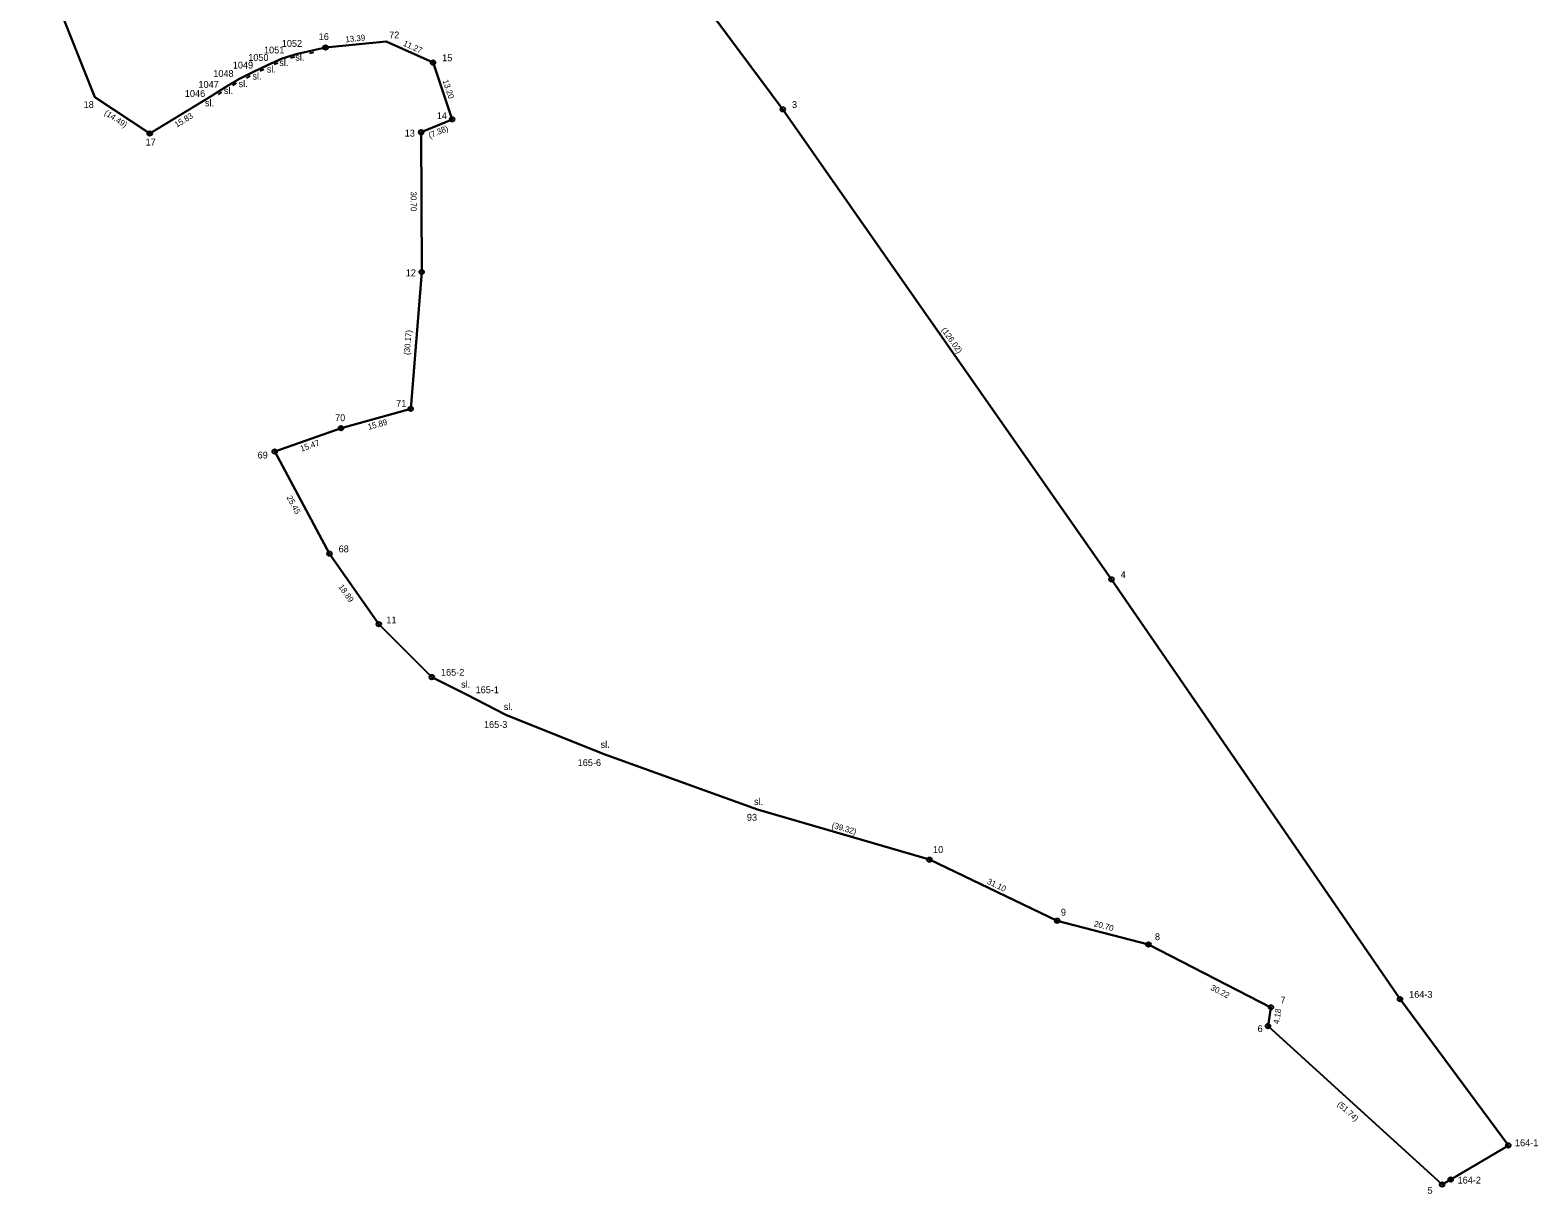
# Model space of a CAD drawing. Extents: x -555170 to -550532, y -1039598 to -1034701.
# Drawn here: x -553100.7 to -552769.4, y -1038100 to -1037844.3 of the extents above; entities that cross this region are included whole.
import ezdxf

# ---------------------------------------------------------------- set-up
doc = ezdxf.new("R2010")
doc.units = 0
for name, color, linetype in [('Vrstva 10', 7, 'Continuous'), ('Vrstva 40', 7, 'Continuous'), ('Vrstva 43', 7, 'Continuous'), ('Vrstva 48', 7, 'Continuous')]:
    doc.layers.add(name, color=color, linetype=linetype)

msp = doc.modelspace()

# ---------------------------------------------------------------- linework, layer by layer
at = {"layer": 'Vrstva 10'}
for p, q in [((-553047.12, -1037851.85), (-553046.31, -1037851.49)), ((-553043.44, -1037850.42), (-553042.58, -1037850.19)), ((-553039.23, -1037849.41), (-553038.37, -1037849.21)), ((-553053.18, -1037854.81), (-553052.39, -1037854.4)), ((-553050.14, -1037853.26), (-553049.34, -1037852.89)), ((-553059.34, -1037858.45), (-553058.58, -1037857.99)), ((-553056.15, -1037856.41), (-553055.39, -1037855.95))]:
    msp.add_line(p, q, dxfattribs=at)
at = {"layer": 'Vrstva 40'}
for p, q in [((-552935.31, -1037861.75), (-552967.96, -1037817.8)), ((-553100.71, -1037823.27), (-553086.52, -1037859.05)), ((-553041.94, -1037849.58), (-553035.79, -1037848.16)), ((-553035.79, -1037848.16), (-553022.47, -1037846.86)), ((-553022.47, -1037846.86), (-553012.18, -1037851.47)), ((-553051.75, -1037853.54), (-553048.52, -1037852.03)), ((-553048.52, -1037852.03), (-553045.34, -1037850.56)), ((-553045.34, -1037850.56), (-553041.94, -1037849.58)), ((-553012.18, -1037851.47), (-553007.97, -1037863.94)), ((-553057.92, -1037856.93), (-553054.87, -1037855.09)), ((-553054.87, -1037855.09), (-553051.75, -1037853.54)), ((-553060.93, -1037858.84), (-553057.92, -1037856.93)), ((-553086.52, -1037859.05), (-553074.43, -1037867.05)), ((-553074.43, -1037867.05), (-553060.93, -1037858.84)), ((-552863.09, -1037965.02), (-552935.31, -1037861.75)), ((-553007.97, -1037863.94), (-553014.78, -1037866.78)), ((-553014.78, -1037866.78), (-553014.68, -1037897.48)), ((-553014.68, -1037897.48), (-553017.09, -1037927.56)), ((-553017.09, -1037927.56), (-553032.4, -1037931.79)), ((-553032.4, -1037931.79), (-553046.98, -1037936.93)), ((-553046.98, -1037936.93), (-553034.93, -1037959.38)), ((-553034.93, -1037959.38), (-553024.08, -1037974.87)), ((-552799.7, -1038057.26), (-552863.09, -1037965.02)), ((-553024.08, -1037974.87), (-553012.44, -1037986.49)), ((-553012.44, -1037986.49), (-553004.83, -1037990.33)), ((-553004.83, -1037990.33), (-552996.15, -1037994.79)), ((-552996.15, -1037994.79), (-552974.77, -1038003.35)), ((-552974.77, -1038003.35), (-552940.85, -1038015.62)), ((-552940.85, -1038015.62), (-552903.1, -1038026.61)), ((-552903.1, -1038026.61), (-552875.05, -1038040.03)), ((-552875.05, -1038040.03), (-552854.97, -1038045.25)), ((-552854.97, -1038045.25), (-552828.06, -1038059.06)), ((-552775.89, -1038089.4), (-552799.7, -1038057.26)), ((-552828.06, -1038059.06), (-552828.71, -1038063.18)), ((-552828.71, -1038063.18), (-552790.43, -1038097.99)), ((-552788.56, -1038096.88), (-552775.89, -1038089.4)), ((-552790.43, -1038097.99), (-552788.56, -1038096.88))]:
    msp.add_line(p, q, dxfattribs=at)
at = {"layer": 'Vrstva 43'}
for p, q in [((-553035.79, -1037848.16), (-553035.79, -1037848.16)), ((-553022.47, -1037846.86), (-553022.47, -1037846.86)), ((-553048.52, -1037852.03), (-553048.52, -1037852.03)), ((-553045.34, -1037850.56), (-553045.34, -1037850.56)), ((-553041.94, -1037849.58), (-553041.94, -1037849.58)), ((-553012.18, -1037851.47), (-553012.18, -1037851.47)), ((-553054.87, -1037855.09), (-553054.87, -1037855.09)), ((-553051.75, -1037853.54), (-553051.75, -1037853.54)), ((-553057.92, -1037856.93), (-553057.92, -1037856.93)), ((-553086.52, -1037859.05), (-553086.52, -1037859.05)), ((-553060.93, -1037858.84), (-553060.93, -1037858.84)), ((-552935.31, -1037861.75), (-552935.31, -1037861.75)), ((-553007.97, -1037863.94), (-553007.97, -1037863.94)), ((-553074.43, -1037867.05), (-553074.43, -1037867.05)), ((-553014.78, -1037866.78), (-553014.78, -1037866.78)), ((-553014.68, -1037897.48), (-553014.68, -1037897.48)), ((-553017.09, -1037927.56), (-553017.09, -1037927.56)), ((-553032.4, -1037931.79), (-553032.4, -1037931.79)), ((-553046.98, -1037936.93), (-553046.98, -1037936.93)), ((-553034.93, -1037959.38), (-553034.93, -1037959.38)), ((-552863.09, -1037965.02), (-552863.09, -1037965.02)), ((-553024.08, -1037974.87), (-553024.08, -1037974.87)), ((-553012.44, -1037986.49), (-553012.44, -1037986.49)), ((-553004.83, -1037990.33), (-553004.83, -1037990.33)), ((-552996.15, -1037994.79), (-552996.15, -1037994.79)), ((-552974.77, -1038003.35), (-552974.77, -1038003.35)), ((-552940.85, -1038015.62), (-552940.85, -1038015.62)), ((-552903.1, -1038026.61), (-552903.1, -1038026.61)), ((-552875.05, -1038040.03), (-552875.05, -1038040.03)), ((-552854.97, -1038045.25), (-552854.97, -1038045.25)), ((-552799.7, -1038057.26), (-552799.7, -1038057.26)), ((-552828.06, -1038059.06), (-552828.06, -1038059.06)), ((-552828.71, -1038063.18), (-552828.71, -1038063.18)), ((-552775.89, -1038089.4), (-552775.89, -1038089.4)), ((-552788.56, -1038096.88), (-552788.56, -1038096.88)), ((-552790.43, -1038097.99), (-552790.43, -1038097.99))]:
    msp.add_line(p, q, dxfattribs=at)
for centre, radius in [((-553035.79, -1037848.16), 0.5), ((-553035.79, -1037848.16), 0.01), ((-553012.18, -1037851.47), 0.5), ((-553012.18, -1037851.47), 0.01), ((-552935.31, -1037861.75), 0.5), ((-552935.31, -1037861.75), 0.01), ((-553007.97, -1037863.94), 0.5), ((-553007.97, -1037863.94), 0.01), ((-553074.43, -1037867.05), 0.5), ((-553074.43, -1037867.05), 0.01), ((-553014.78, -1037866.78), 0.5), ((-553014.78, -1037866.78), 0.01), ((-553014.68, -1037897.48), 0.5), ((-553014.68, -1037897.48), 0.01), ((-553017.09, -1037927.56), 0.5), ((-553017.09, -1037927.56), 0.01), ((-553032.4, -1037931.79), 0.5), ((-553032.4, -1037931.79), 0.01), ((-553046.98, -1037936.93), 0.5), ((-553046.98, -1037936.93), 0.01), ((-553034.93, -1037959.38), 0.5), ((-553034.93, -1037959.38), 0.01), ((-552863.09, -1037965.02), 0.5), ((-552863.09, -1037965.02), 0.01), ((-553024.08, -1037974.87), 0.5), ((-553024.08, -1037974.87), 0.01), ((-553012.44, -1037986.49), 0.5), ((-553012.44, -1037986.49), 0.01), ((-552903.1, -1038026.61), 0.5), ((-552903.1, -1038026.61), 0.01), ((-552875.05, -1038040.03), 0.5), ((-552875.05, -1038040.03), 0.01), ((-552854.97, -1038045.25), 0.5), ((-552854.97, -1038045.25), 0.01), ((-552799.7, -1038057.26), 0.5), ((-552799.7, -1038057.26), 0.01), ((-552828.06, -1038059.06), 0.5), ((-552828.06, -1038059.06), 0.01), ((-552828.71, -1038063.18), 0.5), ((-552828.71, -1038063.18), 0.01), ((-552775.89, -1038089.4), 0.5), ((-552775.89, -1038089.4), 0.01), ((-552788.56, -1038096.88), 0.5), ((-552788.56, -1038096.88), 0.01), ((-552790.43, -1038097.99), 0.5), ((-552790.43, -1038097.99), 0.01)]:
    msp.add_circle(centre, radius, dxfattribs=at)
at = {"layer": 'Vrstva 48'}
msp.add_lwpolyline([(-552967.96, -1037817.8), (-552935.31, -1037861.75), (-552863.09, -1037965.02), (-552799.7, -1038057.26), (-552775.89, -1038089.4), (-552788.56, -1038096.88), (-552790.43, -1038097.99), (-552828.71, -1038063.18), (-552828.06, -1038059.06), (-552854.97, -1038045.25), (-552875.05, -1038040.03), (-552903.1, -1038026.61), (-552940.85, -1038015.62), (-552974.77, -1038003.35), (-552996.15, -1037994.79), (-553004.83, -1037990.33), (-553012.44, -1037986.49), (-553024.08, -1037974.87), (-553034.93, -1037959.38), (-553046.98, -1037936.93), (-553032.4, -1037931.79), (-553017.09, -1037927.56), (-553014.68, -1037897.48), (-553014.78, -1037866.78), (-553007.97, -1037863.94), (-553012.18, -1037851.47), (-553022.47, -1037846.86), (-553035.79, -1037848.16), (-553041.94, -1037849.58), (-553045.34, -1037850.56), (-553048.52, -1037852.03), (-553051.75, -1037853.54), (-553054.87, -1037855.09), (-553057.92, -1037856.93), (-553060.93, -1037858.84), (-553074.43, -1037867.05), (-553086.52, -1037859.05), (-553100.71, -1037823.27)], dxfattribs=at)

# ---------------------------------------------------------------- texts
at = {"layer": 'Vrstva 10'}
for s, rotation, p in [('13.39', 5.5862, (-553031.37, -1037847.03)), ('11.27', 335.8616, (-553018.87, -1037847.71)), ('13.20', 288.6595, (-553010.1, -1037855.44)), ('(14.49)', 326.4913, (-553084.53, -1037862.81)), ('15.83', 31.3058, (-553068.5, -1037865.79)), ('(7.38)', 22.6019, (-553012.88, -1037868.15)), ('30.70', 270.196, (-553017.11, -1037879.8)), ('(30.17)', 85.419, (-553017.31, -1037915.76)), ('(126.02)', 304.9663, (-552900.56, -1037910.21)), ('15.89', 15.449, (-553026.31, -1037932.18)), ('15.47', 19.4109, (-553041.11, -1037936.98)), ('25.45', 298.2345, (-553044.41, -1037947.01)), ('18.89', 305.0094, (-553033.05, -1037966.65)), ('(39.32)', 343.7672, (-552924.67, -1038019.6)), ('31.10', 334.4417, (-552890.56, -1038031.83)), ('20.70', 345.4205, (-552867.04, -1038041.25)), ('30.22', 332.8372, (-552841.46, -1038055.15)), ('4.18', 80.976, (-552826.3, -1038062.8)), ('(51.74)', 317.7252, (-552813.61, -1038080.52))]:
    msp.add_text(s, height=1.3, rotation=rotation, dxfattribs=at).set_placement(p)
at = {"layer": 'Vrstva 43'}
for s, p in [('16', (-553037.31, -1037846.52)), ('72', (-553021.83, -1037846.15)), ('1051', (-553049.33, -1037849.46)), ('1052', (-553045.42, -1037848.01)), ('1049', (-553056.18, -1037852.77)), ('1050', (-553052.79, -1037851.09)), ('sl.', (-553045.97, -1037852.22)), ('sl.', (-553042.45, -1037851.04)), ('15', (-553010.18, -1037851.17)), ('1048', (-553060.47, -1037854.63)), ('sl.', (-553054.92, -1037856.87)), ('sl.', (-553051.87, -1037855.19)), ('sl.', (-553048.71, -1037853.65)), ('1046', (-553066.72, -1037859.01)), ('1047', (-553063.73, -1037857.01)), ('sl.', (-553058.14, -1037858.38)), ('18', (-553088.96, -1037861.45)), ('sl.', (-553062.31, -1037861.07)), ('3', (-552933.31, -1037861.45)), ('14', (-553011.35, -1037863.88)), ('17', (-553075.35, -1037869.69)), ('13', (-553018.4, -1037867.72)), ('12', (-553018.18, -1037898.42)), ('71', (-553020.29, -1037927.08)), ('70', (-553033.71, -1037930.25)), ('69', (-553050.72, -1037938.46)), ('68', (-553032.93, -1037959.08)), ('4', (-552861.09, -1037964.72)), ('11', (-553022.44, -1037974.69)), ('165-2', (-553010.44, -1037986.19)), ('sl.', (-553006.03, -1037988.85)), ('165-1', (-553002.83, -1037990.03)), ('sl.', (-552996.65, -1037993.74)), ('165-3', (-553000.99, -1037997.66)), ('sl.', (-552975.37, -1038002.04)), ('165-6', (-552980.4, -1038006.04)), ('sl.', (-552941.65, -1038014.59)), ('93', (-552943.22, -1038018.05)), ('10', (-552902.32, -1038025.14)), ('9', (-552874.22, -1038038.91)), ('8', (-552853.56, -1038044.29)), ('7', (-552825.96, -1038058.18)), ('164-3', (-552797.7, -1038056.96)), ('6', (-552831, -1038064.5)), ('164-1', (-552774.45, -1038089.57)), ('164-2', (-552787.05, -1038097.77)), ('5', (-552793.65, -1038100.02))]:
    msp.add_text(s, height=1.5, dxfattribs=at).set_placement(p)

doc.saveas('drawing.dxf')
